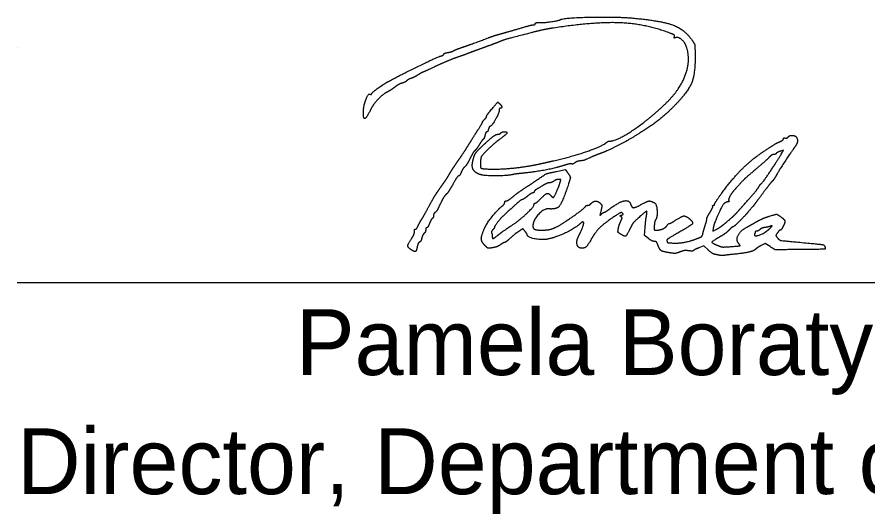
# Model space of a CAD drawing. Extents: x 0 to 36.9, y 0 to 22.
# Drawn here: x 24.5 to 26.309, y 7.199 to 8.256 of the extents above; entities that cross this region are included whole.
import ezdxf

# ---------------------------------------------------------------- set-up
doc = ezdxf.new("R2010")
doc.units = 0
doc.layers.add('SH_Data', color=7, linetype='Continuous')
doc.layers.add('SH_Text', color=7, linetype='Continuous')

msp = doc.modelspace()

# ---------------------------------------------------------------- linework, layer by layer
at = {"layer": 'SH_Data'}
for p, q in [((24.5, 8.191), (24.5, 8.191)), ((24.5, 7.691), (28, 7.691))]:
    msp.add_line(p, q, dxfattribs=at)
at = {"layer": 'SH_Text'}
for points in [[(26.1247, 7.9638), (26.13, 7.9727), (26.1227, 7.9702)], [(25.6473, 7.9276), (25.6653, 7.9317), (25.67, 7.9255)], [(25.8423, 7.7848), (25.834, 7.7912), (25.8354, 7.8082)], [(25.9803, 7.8068), (25.9793, 7.8004), (25.9879, 7.8048)], [(25.9692, 7.7605), (25.9601, 7.7688), (25.9495, 7.7647)], [(26.1011, 7.7675), (26.0905, 7.7743), (26.0821, 7.7698)]]:
    msp.add_lwpolyline(points, dxfattribs=at)
for points in [[(25.6547, 8.2502), (25.6615, 8.2544), (25.7785, 8.2567), (25.8129, 8.2533)], [(25.8129, 8.2533), (25.8722, 8.2475), (25.9197, 8.2292), (25.9355, 8.2061)], [(25.565, 8.2306), (25.5811, 8.2354), (25.5959, 8.2393), (25.598, 8.2393)], [(25.598, 8.2393), (25.6001, 8.2393), (25.6017, 8.2404), (25.6017, 8.2418)], [(25.6017, 8.2418), (25.6017, 8.2432), (25.6058, 8.2442), (25.6107, 8.244)], [(25.6107, 8.244), (25.6203, 8.2437), (25.6513, 8.2481), (25.6547, 8.2502)], [(25.8854, 8.2226), (25.8349, 8.2416), (25.7269, 8.2456), (25.6365, 8.2318)], [(25.5021, 8.2116), (25.5101, 8.2146), (25.5209, 8.2181), (25.5261, 8.2195)], [(25.5261, 8.2195), (25.5314, 8.2209), (25.5489, 8.2259), (25.565, 8.2306)], [(25.5921, 8.2221), (25.5411, 8.2089), (25.5369, 8.2077), (25.5261, 8.2033)], [(25.6365, 8.2318), (25.6273, 8.2304), (25.6073, 8.226), (25.5921, 8.2221)], [(25.8978, 8.2139), (25.8987, 8.2165), (25.8953, 8.2189), (25.8854, 8.2226)], [(25.4457, 8.1911), (25.4605, 8.1962), (25.4669, 8.1985), (25.5021, 8.2116)], [(25.5261, 8.2033), (25.5235, 8.2022), (25.5132, 8.1984), (25.5033, 8.1948)], [(25.9002, 8.2119), (25.8976, 8.2109), (25.8968, 8.2115), (25.8978, 8.2139)], [(25.9235, 8.192), (25.9203, 8.2017), (25.9058, 8.214), (25.9002, 8.2119)], [(25.9355, 8.2061), (25.9405, 8.1989), (25.9414, 8.1946), (25.9417, 8.1767)], [(25.4073, 8.1768), (25.4073, 8.1779), (25.4114, 8.1795), (25.4163, 8.1804)], [(25.4163, 8.1804), (25.4213, 8.1814), (25.4264, 8.1829), (25.4277, 8.1839)], [(25.4277, 8.1839), (25.4291, 8.1849), (25.4372, 8.1881), (25.4457, 8.1911)], [(25.4697, 8.1824), (25.4612, 8.1792), (25.445, 8.1733), (25.4337, 8.1693)], [(25.5033, 8.1948), (25.4934, 8.1912), (25.4783, 8.1856), (25.4697, 8.1824)], [(25.878, 8.0708), (25.909, 8.1002), (25.9328, 8.1637), (25.9235, 8.192)], [(25.2897, 8.1189), (25.32, 8.1351), (25.3936, 8.1708), (25.4019, 8.1732)], [(25.4337, 8.1693), (25.4225, 8.1653), (25.4022, 8.1567), (25.3885, 8.1503)], [(25.4019, 8.1732), (25.4049, 8.1741), (25.4073, 8.1757), (25.4073, 8.1768)], [(25.9417, 8.1767), (25.9425, 8.1359), (25.9264, 8.0962), (25.897, 8.0663)], [(25.3885, 8.1503), (25.3749, 8.1438), (25.3632, 8.1385), (25.3627, 8.1385)], [(25.3379, 8.1253), (25.3346, 8.1243), (25.3305, 8.122), (25.3287, 8.1202)], [(25.3527, 8.1328), (25.3478, 8.1297), (25.3411, 8.1263), (25.3379, 8.1253)], [(25.3627, 8.1385), (25.3621, 8.1385), (25.3576, 8.1359), (25.3527, 8.1328)], [(25.2537, 8.0923), (25.2537, 8.0944), (25.2791, 8.1132), (25.2897, 8.1189)], [(25.3041, 8.1073), (25.2995, 8.1037), (25.2924, 8.099), (25.2883, 8.0969)], [(25.319, 8.1153), (25.3154, 8.1145), (25.3088, 8.1108), (25.3041, 8.1073)], [(25.3287, 8.1202), (25.3269, 8.1184), (25.3225, 8.1162), (25.319, 8.1153)], [(25.2366, 8.0544), (25.2367, 8.0676), (25.2473, 8.0942), (25.2514, 8.0916)], [(25.2514, 8.0916), (25.2527, 8.0908), (25.2537, 8.0911), (25.2537, 8.0923)], [(25.2883, 8.0969), (25.2778, 8.0916), (25.2579, 8.0707), (25.2517, 8.0586)], [(25.5039, 8.0533), (25.5225, 8.0755), (25.5218, 8.0749), (25.5259, 8.0715)], [(25.5259, 8.0715), (25.5302, 8.068), (25.5311, 8.0617), (25.5273, 8.0617)], [(25.7613, 7.9921), (25.7754, 7.9921), (25.8435, 8.038), (25.878, 8.0708)], [(25.2379, 8.0407), (25.2371, 8.0415), (25.2365, 8.0477), (25.2366, 8.0544)], [(25.2517, 8.0586), (25.2451, 8.0457), (25.2398, 8.0388), (25.2379, 8.0407)], [(25.4985, 8.0447), (25.4985, 8.0459), (25.501, 8.0498), (25.5039, 8.0533)], [(25.5249, 8.0566), (25.5249, 8.0511), (25.509, 8.0233), (25.5058, 8.0233)], [(25.5273, 8.0617), (25.526, 8.0617), (25.5249, 8.0594), (25.5249, 8.0566)], [(25.897, 8.0663), (25.8784, 8.0474), (25.846, 8.0225), (25.8155, 8.0037)], [(25.49, 8.0329), (25.4894, 8.0329), (25.4911, 8.035), (25.4937, 8.0377)], [(25.4937, 8.0377), (25.4964, 8.0403), (25.4985, 8.0435), (25.4985, 8.0447)], [(25.4589, 7.9822), (25.4655, 7.9929), (25.4755, 8.0086), (25.481, 8.0172)], [(25.481, 8.0172), (25.4865, 8.0258), (25.4906, 8.0329), (25.49, 8.0329)], [(25.5024, 8.0173), (25.5015, 8.014), (25.4999, 8.0113), (25.4987, 8.0113)], [(25.5058, 8.0233), (25.5047, 8.0233), (25.5032, 8.0206), (25.5024, 8.0173)], [(25.4901, 7.9823), (25.5058, 7.9969), (25.5186, 8.0065), (25.5225, 8.0065)], [(25.4949, 8.0041), (25.4941, 8.0002), (25.4923, 7.9963), (25.4911, 7.9955)], [(25.4987, 8.0113), (25.4975, 8.0113), (25.4958, 8.0081), (25.4949, 8.0041)], [(25.5225, 8.0065), (25.525, 8.0065), (25.5277, 8.0076), (25.5285, 8.0089)], [(25.5417, 8.0093), (25.5417, 8.0081), (25.535, 8.0022), (25.5267, 7.9961)], [(25.5285, 8.0089), (25.5303, 8.0118), (25.5417, 8.0121), (25.5417, 8.0093)], [(25.8155, 8.0037), (25.7963, 7.9918), (25.755, 7.9709), (25.7409, 7.9658)], [(26.1297, 7.997), (26.1297, 7.9986), (26.1313, 7.9992), (26.1332, 7.9985)], [(26.1332, 7.9985), (26.1351, 7.9978), (26.1379, 7.9987), (26.1395, 8.0006)], [(26.1395, 8.0006), (26.141, 8.0025), (26.1447, 8.0041), (26.1477, 8.0041)], [(26.1477, 8.0041), (26.1571, 8.0041), (26.1608, 7.988), (26.1534, 7.9791)], [(25.4372, 7.9493), (25.4426, 7.9568), (25.4523, 7.9716), (25.4589, 7.9822)], [(25.4688, 7.9477), (25.4716, 7.9607), (25.4777, 7.9707), (25.4901, 7.9823)], [(25.4826, 7.9841), (25.4792, 7.9786), (25.4751, 7.973), (25.4734, 7.9717)], [(25.4911, 7.9955), (25.4898, 7.9947), (25.486, 7.9896), (25.4826, 7.9841)], [(25.5267, 7.9961), (25.5185, 7.99), (25.506, 7.9792), (25.499, 7.972)], [(25.6413, 7.9502), (25.6783, 7.9584), (25.7445, 7.9812), (25.7531, 7.9888)], [(25.7531, 7.9888), (25.7552, 7.9906), (25.7589, 7.9921), (25.7613, 7.9921)], [(26.093, 7.9737), (26.1119, 7.986), (26.1138, 7.987), (26.1219, 7.9907)], [(26.1534, 7.9791), (26.1493, 7.974), (26.1164, 7.9236), (26.1133, 7.9174)], [(26.1219, 7.9907), (26.1262, 7.9927), (26.1297, 7.9955), (26.1297, 7.997)], [(25.4734, 7.9717), (25.4717, 7.9703), (25.4671, 7.9627), (25.4631, 7.9547)], [(25.499, 7.972), (25.4882, 7.9611), (25.4861, 7.9574), (25.4855, 7.9491)], [(25.7409, 7.9658), (25.7363, 7.9641), (25.7293, 7.9613), (25.7253, 7.9596)], [(25.9983, 7.8812), (26.0206, 7.912), (26.0656, 7.956), (26.093, 7.9737)], [(26.0819, 7.9009), (26.0847, 7.9028), (26.1129, 7.9443), (26.1247, 7.9638)], [(26.1087, 7.9633), (26.1065, 7.9633), (26.1025, 7.9609), (26.0998, 7.9579)], [(26.114, 7.9655), (26.1133, 7.9643), (26.1109, 7.9633), (26.1087, 7.9633)], [(26.1227, 7.9702), (26.1186, 7.9688), (26.1147, 7.9666), (26.114, 7.9655)], [(25.4205, 7.9237), (25.4243, 7.9303), (25.4318, 7.9418), (25.4372, 7.9493)], [(25.4631, 7.9547), (25.459, 7.9467), (25.454, 7.9387), (25.4518, 7.9369)], [(25.4841, 7.9209), (25.4737, 7.9248), (25.4666, 7.9372), (25.4688, 7.9477)], [(25.4855, 7.9491), (25.4847, 7.9357), (25.4887, 7.9328), (25.5093, 7.9323)], [(25.6077, 7.9427), (25.6157, 7.9444), (25.6308, 7.9478), (25.6413, 7.9502)], [(25.6791, 7.9434), (25.6775, 7.944), (25.6694, 7.9423), (25.6611, 7.9397)], [(25.6859, 7.9456), (25.6838, 7.9438), (25.6808, 7.9428), (25.6791, 7.9434)], [(25.6967, 7.9497), (25.6929, 7.9492), (25.688, 7.9474), (25.6859, 7.9456)], [(25.7253, 7.9596), (25.7083, 7.9521), (25.7034, 7.9504), (25.6967, 7.9497)], [(26.0998, 7.9579), (26.0971, 7.9549), (26.0847, 7.9439), (26.0721, 7.9333)], [(25.4445, 7.9257), (25.4427, 7.9213), (25.4401, 7.9177), (25.4388, 7.9177)], [(25.4518, 7.9369), (25.4496, 7.9351), (25.4464, 7.9301), (25.4445, 7.9257)], [(25.5093, 7.9323), (25.5286, 7.9318), (25.5864, 7.9379), (25.6077, 7.9427)], [(25.6611, 7.9397), (25.6447, 7.9344), (25.5996, 7.9259), (25.5758, 7.9236)], [(25.5933, 7.9012), (25.625, 7.9223), (25.6264, 7.9229), (25.6473, 7.9276)], [(25.67, 7.9255), (25.6766, 7.9168), (25.6765, 7.9119), (25.6687, 7.8893)], [(26.0721, 7.9333), (26.0525, 7.9168), (26.0408, 7.9054), (26.0241, 7.8865)], [(25.4074, 7.903), (25.4108, 7.9078), (25.4166, 7.9171), (25.4205, 7.9237)], [(25.4388, 7.9177), (25.4375, 7.9177), (25.4321, 7.9098), (25.4268, 7.9001)], [(25.5554, 7.921), (25.5417, 7.9179), (25.4922, 7.9179), (25.4841, 7.9209)], [(25.5758, 7.9236), (25.5674, 7.9228), (25.5583, 7.9216), (25.5554, 7.921)], [(25.6415, 7.9068), (25.6389, 7.9049), (25.635, 7.9033), (25.6328, 7.9033)], [(25.6514, 7.9104), (25.6485, 7.9104), (25.644, 7.9087), (25.6415, 7.9068)], [(25.6547, 7.9039), (25.6564, 7.9097), (25.656, 7.9105), (25.6514, 7.9104)], [(26.1133, 7.9174), (26.1115, 7.914), (26.1076, 7.9085), (26.1046, 7.9053)], [(25.3939, 7.8838), (25.398, 7.8897), (25.4041, 7.8983), (25.4074, 7.903)], [(25.4268, 7.9001), (25.4215, 7.8905), (25.4148, 7.8805), (25.4119, 7.8779)], [(25.5541, 7.8733), (25.5678, 7.8844), (25.5659, 7.883), (25.5933, 7.9012)], [(25.623, 7.9002), (25.6086, 7.8922), (25.5993, 7.8858), (25.5993, 7.8839)], [(25.6328, 7.9033), (25.6305, 7.9033), (25.6261, 7.9019), (25.623, 7.9002)], [(25.6687, 7.8893), (25.6585, 7.8594), (25.6465, 7.8464), (25.6305, 7.8477)], [(25.64, 7.8721), (25.6418, 7.8721), (25.6515, 7.8932), (25.6547, 7.9039)], [(26.0466, 7.8579), (26.062, 7.875), (26.0755, 7.8914), (26.0779, 7.8957)], [(26.0779, 7.8957), (26.0791, 7.8979), (26.0809, 7.9002), (26.0819, 7.9009)], [(26.1046, 7.9053), (26.1017, 7.9021), (26.0928, 7.8907), (26.0849, 7.8801)], [(25.375, 7.8517), (25.3813, 7.8636), (25.3898, 7.878), (25.3939, 7.8838)], [(25.4119, 7.8779), (25.4091, 7.8754), (25.4036, 7.8663), (25.3996, 7.8577)], [(25.5403, 7.8649), (25.5422, 7.8649), (25.5484, 7.8687), (25.5541, 7.8733)], [(25.5849, 7.8745), (25.5799, 7.8705), (25.5749, 7.8673), (25.5738, 7.8673)], [(25.5967, 7.8817), (25.5952, 7.8817), (25.5899, 7.8784), (25.5849, 7.8745)], [(25.5993, 7.8839), (25.5993, 7.8827), (25.5981, 7.8817), (25.5967, 7.8817)], [(25.6137, 7.8697), (25.6239, 7.8798), (25.6304, 7.8816), (25.6353, 7.8757)], [(25.6353, 7.8757), (25.637, 7.8737), (25.6391, 7.8721), (25.64, 7.8721)], [(25.9833, 7.8579), (25.9833, 7.8593), (25.9901, 7.8698), (25.9983, 7.8812)], [(26.0241, 7.8865), (26.0183, 7.8799), (26.012, 7.867), (26.0135, 7.8647)], [(26.0849, 7.8801), (26.077, 7.8694), (26.0693, 7.8592), (26.0678, 7.8574)], [(25.3996, 7.8577), (25.3957, 7.8491), (25.391, 7.8412), (25.3891, 7.8402)], [(25.4935, 7.8054), (25.4979, 7.8159), (25.5212, 7.8453), (25.5315, 7.8537)], [(25.5315, 7.8537), (25.5345, 7.8561), (25.5369, 7.8596), (25.5369, 7.8615)], [(25.5369, 7.8615), (25.5369, 7.8633), (25.5385, 7.8649), (25.5403, 7.8649)], [(25.5738, 7.8673), (25.5719, 7.8673), (25.5634, 7.86), (25.5381, 7.8368)], [(25.5533, 7.8135), (25.5689, 7.8239), (25.5993, 7.8527), (25.5993, 7.857)], [(25.5993, 7.857), (25.5993, 7.8587), (25.6004, 7.8601), (25.6017, 7.8601)], [(25.6017, 7.8601), (25.6031, 7.8601), (25.6085, 7.8644), (25.6137, 7.8697)], [(25.7081, 7.8522), (25.7091, 7.8539), (25.7115, 7.8553), (25.7133, 7.8553)], [(25.7133, 7.8553), (25.7151, 7.8553), (25.7184, 7.857), (25.7205, 7.8592)], [(25.7205, 7.8592), (25.7255, 7.8642), (25.7355, 7.8642), (25.7404, 7.8593)], [(25.7404, 7.8593), (25.7436, 7.8561), (25.7438, 7.8536), (25.7417, 7.8445)], [(25.7585, 7.8466), (25.7788, 7.8618), (25.8015, 7.8674), (25.8045, 7.8579)], [(25.8045, 7.8579), (25.8069, 7.8504), (25.815, 7.8502), (25.8282, 7.8576)], [(25.8282, 7.8576), (25.8402, 7.8642), (25.8474, 7.8649), (25.8557, 7.8603)], [(25.8557, 7.8603), (25.86, 7.8579), (25.8617, 7.8299), (25.8578, 7.8247)], [(25.9736, 7.841), (25.9774, 7.8473), (25.98, 7.8531), (25.9792, 7.8539)], [(25.9792, 7.8539), (25.9784, 7.8546), (25.979, 7.8553), (25.9805, 7.8553)], [(25.9805, 7.8553), (25.9821, 7.8553), (25.9833, 7.8564), (25.9833, 7.8579)], [(26.0112, 7.8625), (26.0049, 7.8625), (25.9953, 7.8473), (25.9833, 7.8181)], [(26.0135, 7.8647), (26.0142, 7.8635), (26.0132, 7.8625), (26.0112, 7.8625)], [(26.031, 7.8405), (26.0342, 7.844), (26.0412, 7.8519), (26.0466, 7.8579)], [(26.0678, 7.8574), (26.0546, 7.841), (26.05, 7.8358), (26.0381, 7.8236)], [(25.3595, 7.8241), (25.3618, 7.8274), (25.3687, 7.8398), (25.375, 7.8517)], [(25.3891, 7.8402), (25.3873, 7.8391), (25.3857, 7.8362), (25.3857, 7.8337)], [(25.5381, 7.8368), (25.529, 7.8284), (25.5153, 7.8113), (25.5153, 7.8083)], [(25.6305, 7.8477), (25.6201, 7.8486), (25.5969, 7.8232), (25.5969, 7.811)], [(25.6653, 7.8204), (25.6839, 7.8328), (25.7063, 7.8495), (25.7081, 7.8522)], [(25.7417, 7.8445), (25.7393, 7.8342), (25.7394, 7.8338), (25.7432, 7.8372)], [(25.7432, 7.8372), (25.7455, 7.8392), (25.7481, 7.8409), (25.7491, 7.8409)], [(25.7491, 7.8409), (25.7501, 7.8409), (25.7543, 7.8435), (25.7585, 7.8466)], [(25.7872, 7.8388), (25.7854, 7.8406), (25.7795, 7.8379), (25.767, 7.8294)], [(25.7843, 7.8312), (25.7821, 7.8325), (25.7824, 7.8334), (25.7855, 7.8346)], [(25.7855, 7.8346), (25.7885, 7.8358), (25.789, 7.837), (25.7872, 7.8388)], [(25.8283, 7.8348), (25.8124, 7.8207), (25.8086, 7.8163), (25.8031, 7.805)], [(25.8384, 7.8331), (25.8402, 7.8425), (25.8376, 7.843), (25.8283, 7.8348)], [(25.9666, 7.8262), (25.9665, 7.8281), (25.9697, 7.8347), (25.9736, 7.841)], [(26.0109, 7.8216), (26.0189, 7.8284), (26.0279, 7.8369), (26.031, 7.8405)], [(26.1002, 7.8323), (26.1143, 7.8365), (26.1155, 7.8366), (26.1213, 7.8327)], [(25.3527, 7.8115), (25.3542, 7.8151), (25.3573, 7.8208), (25.3595, 7.8241)], [(25.377, 7.8167), (25.3749, 7.8115), (25.3723, 7.8073), (25.3711, 7.8073)], [(25.3832, 7.8276), (25.3819, 7.8268), (25.379, 7.8219), (25.377, 7.8167)], [(25.3857, 7.8337), (25.3857, 7.8312), (25.3846, 7.8285), (25.3832, 7.8276)], [(25.6169, 7.8025), (25.6299, 7.8025), (25.649, 7.8095), (25.6653, 7.8204)], [(25.6973, 7.8163), (25.6877, 7.8071), (25.649, 7.7883), (25.6305, 7.7839)], [(25.6944, 7.7905), (25.6985, 7.7982), (25.7049, 7.8144), (25.7049, 7.8172)], [(25.7049, 7.8172), (25.7049, 7.8202), (25.701, 7.8198), (25.6973, 7.8163)], [(25.767, 7.8294), (25.7472, 7.8159), (25.73, 7.7989), (25.7217, 7.7845)], [(25.7786, 7.8057), (25.7793, 7.8099), (25.7816, 7.8169), (25.7836, 7.8213)], [(25.7836, 7.8213), (25.7865, 7.8276), (25.7867, 7.8297), (25.7843, 7.8312)], [(25.8354, 7.8082), (25.8362, 7.8176), (25.8375, 7.8288), (25.8384, 7.8331)], [(25.8578, 7.8247), (25.8566, 7.823), (25.8553, 7.8174), (25.8549, 7.8121)], [(25.8818, 7.812), (25.8837, 7.8147), (25.8862, 7.8169), (25.8874, 7.8169)], [(25.8874, 7.8169), (25.8886, 7.8169), (25.8947, 7.8201), (25.9009, 7.8241)], [(25.9292, 7.8271), (25.9388, 7.8194), (25.932, 7.8115), (25.9004, 7.7938)], [(25.9009, 7.8241), (25.9139, 7.8323), (25.9215, 7.8331), (25.9292, 7.8271)], [(25.963, 7.8121), (25.965, 7.818), (25.9666, 7.8244), (25.9666, 7.8262)], [(25.9833, 7.8181), (25.9822, 7.8154), (25.9808, 7.8104), (25.9803, 7.8068)], [(25.9879, 7.8048), (25.9927, 7.8072), (26.003, 7.8148), (26.0109, 7.8216)], [(26.0381, 7.8236), (26.0306, 7.816), (26.0236, 7.8097), (26.0225, 7.8097)], [(26.0514, 7.8086), (26.0542, 7.8102), (26.063, 7.8151), (26.0709, 7.8196)], [(26.0709, 7.8196), (26.0789, 7.8242), (26.092, 7.8299), (26.1002, 7.8323)], [(26.1213, 7.8327), (26.131, 7.8264), (26.1334, 7.819), (26.1287, 7.81)], [(25.3391, 7.785), (25.3423, 7.7897), (25.3449, 7.7961), (25.3449, 7.7992)], [(25.3449, 7.7992), (25.3449, 7.8023), (25.346, 7.8049), (25.3474, 7.8049)], [(25.3474, 7.8049), (25.3487, 7.8049), (25.3511, 7.8079), (25.3527, 7.8115)], [(25.3689, 7.8028), (25.3689, 7.8003), (25.3674, 7.797), (25.3655, 7.7954)], [(25.3711, 7.8073), (25.3699, 7.8073), (25.3689, 7.8053), (25.3689, 7.8028)], [(25.4951, 7.7697), (25.4875, 7.7773), (25.4869, 7.7901), (25.4935, 7.8054)], [(25.5116, 7.8032), (25.5095, 7.8012), (25.5085, 7.7979), (25.5092, 7.796)], [(25.5153, 7.8083), (25.5153, 7.8076), (25.5137, 7.8053), (25.5116, 7.8032)], [(25.5218, 7.7912), (25.5293, 7.7973), (25.5345, 7.801), (25.5533, 7.8135)], [(25.5691, 7.8013), (25.5608, 7.7959), (25.5583, 7.7939), (25.5471, 7.7839)], [(25.5803, 7.7999), (25.5759, 7.8057), (25.5758, 7.8057), (25.5691, 7.8013)], [(25.5849, 7.7925), (25.5849, 7.7934), (25.5828, 7.7967), (25.5803, 7.7999)], [(25.5969, 7.811), (25.5969, 7.8058), (25.6048, 7.8025), (25.6169, 7.8025)], [(25.7832, 7.7942), (25.7782, 7.7974), (25.7774, 7.7994), (25.7786, 7.8057)], [(25.8031, 7.805), (25.7965, 7.7912), (25.7916, 7.7886), (25.7832, 7.7942)], [(25.8549, 7.8121), (25.8544, 7.8045), (25.8551, 7.8025), (25.8582, 7.8025)], [(25.8582, 7.8025), (25.8665, 7.8025), (25.8785, 7.8073), (25.8818, 7.812)], [(25.9583, 7.795), (25.959, 7.7985), (25.9611, 7.8061), (25.963, 7.8121)], [(26.014, 7.8027), (26.0104, 7.7989), (26.0023, 7.7928), (25.996, 7.7891)], [(26.0225, 7.8097), (26.0214, 7.8097), (26.0176, 7.8066), (26.014, 7.8027)], [(26.0343, 7.7742), (26.0283, 7.7816), (26.0381, 7.8014), (26.0514, 7.8086)], [(26.0683, 7.7943), (26.0658, 7.7878), (26.0913, 7.7968), (26.0997, 7.8054)], [(26.0697, 7.7991), (26.0697, 7.7985), (26.0691, 7.7964), (26.0683, 7.7943)], [(26.0726, 7.8001), (26.071, 7.8001), (26.0697, 7.7996), (26.0697, 7.7991)], [(26.0793, 7.8037), (26.0772, 7.8017), (26.0741, 7.8001), (26.0726, 7.8001)], [(26.0903, 7.8082), (26.0865, 7.8077), (26.0815, 7.8057), (26.0793, 7.8037)], [(26.1021, 7.8109), (26.0995, 7.8099), (26.0942, 7.8087), (26.0903, 7.8082)], [(26.0997, 7.8054), (26.1052, 7.811), (26.1058, 7.8123), (26.1021, 7.8109)], [(26.1228, 7.8025), (26.1216, 7.8025), (26.119, 7.7999), (26.1169, 7.7967)], [(26.1287, 7.81), (26.1266, 7.8059), (26.1239, 7.8025), (26.1228, 7.8025)], [(25.3375, 7.7613), (25.3304, 7.7661), (25.3309, 7.7729), (25.3391, 7.785)], [(25.3605, 7.7854), (25.3596, 7.7814), (25.3575, 7.7776), (25.3558, 7.777)], [(25.3655, 7.7954), (25.3636, 7.7938), (25.3613, 7.7893), (25.3605, 7.7854)], [(25.5092, 7.796), (25.5099, 7.7941), (25.5105, 7.791), (25.5105, 7.7891)], [(25.5105, 7.7891), (25.5105, 7.7842), (25.514, 7.7849), (25.5218, 7.7912)], [(25.5471, 7.7839), (25.5423, 7.7796), (25.5374, 7.7761), (25.5363, 7.7761)], [(25.6305, 7.7839), (25.6177, 7.7808), (25.5851, 7.787), (25.5849, 7.7925)], [(25.7011, 7.7641), (25.6927, 7.7641), (25.6887, 7.7799), (25.6944, 7.7905)], [(25.7217, 7.7845), (25.7136, 7.7704), (25.7072, 7.7641), (25.7011, 7.7641)], [(25.8553, 7.7785), (25.8527, 7.7785), (25.8469, 7.7813), (25.8423, 7.7848)], [(25.9004, 7.7938), (25.8872, 7.7864), (25.881, 7.7816), (25.8818, 7.7794)], [(25.8957, 7.775), (25.9063, 7.7744), (25.9324, 7.7793), (25.9456, 7.7844)], [(25.9456, 7.7844), (25.9544, 7.7878), (25.9573, 7.7902), (25.9583, 7.795)], [(25.996, 7.7891), (25.978, 7.7787), (25.977, 7.7754), (25.9899, 7.7699)], [(26.1169, 7.7967), (26.1134, 7.7913), (26.1134, 7.7904), (26.1172, 7.7857)], [(26.1172, 7.7857), (26.1209, 7.7812), (26.1259, 7.7802), (26.1598, 7.7771)], [(25.3511, 7.7678), (25.3493, 7.758), (25.3451, 7.756), (25.3375, 7.7613)], [(25.3558, 7.777), (25.354, 7.7763), (25.3519, 7.7722), (25.3511, 7.7678)], [(25.5113, 7.7651), (25.5026, 7.7637), (25.5005, 7.7643), (25.4951, 7.7697)], [(25.5278, 7.7714), (25.5243, 7.7688), (25.5168, 7.7659), (25.5113, 7.7651)], [(25.5363, 7.7761), (25.5352, 7.7761), (25.5314, 7.774), (25.5278, 7.7714)], [(25.8628, 7.7707), (25.8609, 7.7759), (25.8584, 7.7785), (25.8553, 7.7785)], [(25.8882, 7.7542), (25.8731, 7.7566), (25.8663, 7.761), (25.8628, 7.7707)], [(25.8818, 7.7794), (25.8831, 7.776), (25.8838, 7.7757), (25.8957, 7.775)], [(25.9495, 7.7647), (25.9437, 7.7625), (25.9386, 7.7599), (25.9382, 7.759)], [(25.9899, 7.7699), (25.9968, 7.767), (26.0032, 7.7664), (26.0167, 7.7675)], [(26.0167, 7.7675), (26.0363, 7.769), (26.038, 7.7697), (26.0343, 7.7742)], [(26.0704, 7.762), (26.0666, 7.7582), (26.0452, 7.7534), (26.0217, 7.7509)], [(26.0821, 7.7698), (26.0775, 7.7673), (26.0722, 7.7638), (26.0704, 7.762)], [(26.1477, 7.7611), (26.112, 7.7607), (26.1117, 7.7608), (26.1011, 7.7675)], [(26.218, 7.7662), (26.2188, 7.762), (26.2169, 7.7618), (26.1477, 7.7611)], [(26.1598, 7.7771), (26.2088, 7.7725), (26.2171, 7.771), (26.218, 7.7662)], [(25.9093, 7.7561), (25.9023, 7.7533), (25.8967, 7.7528), (25.8882, 7.7542)], [(25.9281, 7.7586), (25.9224, 7.7594), (25.9151, 7.7584), (25.9093, 7.7561)], [(25.9382, 7.759), (25.9378, 7.7581), (25.9333, 7.7579), (25.9281, 7.7586)], [(25.9839, 7.751), (25.9809, 7.7517), (25.9743, 7.7559), (25.9692, 7.7605)], [(25.9941, 7.7489), (25.9915, 7.7494), (25.9869, 7.7504), (25.9839, 7.751)], [(26.0025, 7.7486), (26.0006, 7.7482), (25.9968, 7.7483), (25.9941, 7.7489)], [(26.0217, 7.7509), (26.0132, 7.7501), (26.0045, 7.749), (26.0025, 7.7486)]]:
    msp.add_open_spline(points, degree=2, dxfattribs=at)

# ---------------------------------------------------------------- texts
for s, p in [('Pamela Boratyn', (25.0928, 7.4943)), ('Director, Department of Transportation', (24.5, 7.241))]:
    msp.add_text(s, height=0.14, dxfattribs=at).set_placement(p)

doc.saveas('drawing.dxf')
